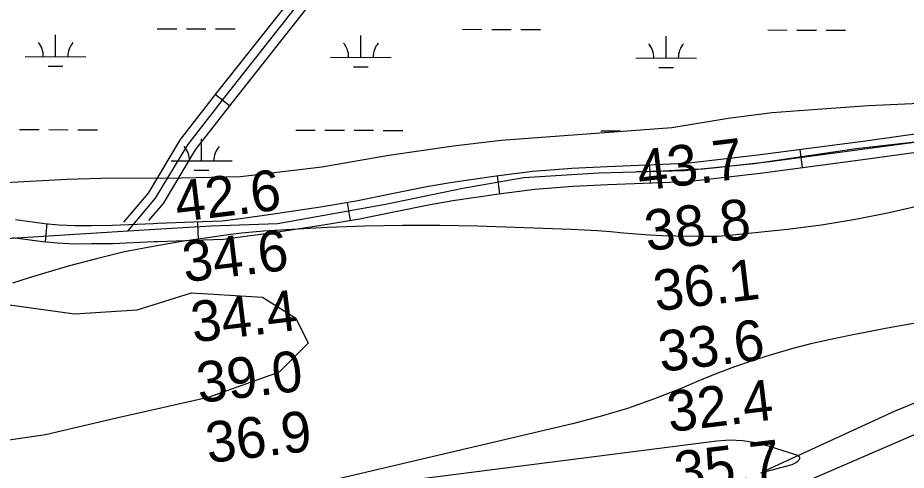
# Model space of a CAD drawing. Extents: x 3219052 to 3256913, y 800770 to 826146.
# Drawn here: x 3224915 to 3226376, y 816866 to 817611 of the extents above; entities that cross this region are included whole.
import ezdxf

# ---------------------------------------------------------------- set-up
doc = ezdxf.new("R2010")
doc.units = 0
for name, color, linetype in [('V-RIVR-IDEN', 7, 'Continuous'), ('V-RIVR-RANG', 7, 'Continuous'), ('V-ROAD-CNTR', 7, 'Continuous'), ('V-SITE-VEGE', 7, 'Continuous'), ('V-TOPO-MAJR', 7, 'Continuous'), ('V-TOPO-MINR', 7, 'Continuous'), ('V-WETL-SWMP', 7, 'Continuous')]:
    doc.layers.add(name, color=color, linetype=linetype)

msp = doc.modelspace()

# ---------------------------------------------------------------- linework, layer by layer
at = {"layer": 'V-ROAD-CNTR'}
for p, q in [((3225263.4, 817465.8), (3225239.7, 817484.1)), ((3226200.9, 817393.8), (3226204.8, 817364.1)), ((3225953.7, 817368.6), (3225954.9, 817338.7)), ((3225703.2, 817350.5), (3225707.1, 817320.7)), ((3225456.6, 817306.6), (3225461.6, 817277)), ((3224963, 817271.9), (3224960.2, 817242)), ((3225210.8, 817274.8), (3225211.9, 817244.8))]:
    msp.add_line(p, q, dxfattribs=at)
for points in [[(3225096.1, 817259.6), (3225141.6, 817313.4), (3225194.6, 817401.5), (3225255.4, 817479.9), (3225392.8, 817654.3), (3225582.5, 817917.4), (3225715.9, 818121.1), (3225842, 818314.9), (3225902.1, 818437.2), (3225914.8, 818521.2), (3225906.7, 818658.5), (3225884.4, 818797), (3225888.1, 818985.3), (3225907, 819138.9), (3225923.6, 819231.3), (3225968.7, 819301), (3226035.2, 819352.3), (3226084, 819382.3), (3226185.7, 819414.7), (3226404.9, 819451.8)], [(3226408.4, 819437.2), (3226189.2, 819400), (3226090.3, 819368.6), (3226043.7, 819339.9), (3225979.9, 819290.7), (3225937.8, 819225.7), (3225921.8, 819136.7), (3225903.1, 818984.3), (3225899.4, 818798.1), (3225921.7, 818660.2), (3225929.8, 818520.5), (3225916.5, 818432.7), (3225855.1, 818307.5), (3225728.5, 818112.9), (3225594.9, 817908.9), (3225404.8, 817645.3), (3225267.2, 817470.7), (3225207, 817393), (3225153.9, 817304.6), (3225130.3, 817276.8)], [(3225872.4, 818777.2), (3225891.8, 818656.9), (3225899.7, 818521.9), (3225887.6, 818441.7), (3225829, 818322.3), (3225703.3, 818129.3), (3225570.2, 817925.9), (3225380.9, 817663.3), (3225243.6, 817489.1), (3225182.2, 817410), (3225129.4, 817322.1), (3225088.8, 817274.2)], [(3224911.6, 817278.6), (3224959.1, 817272.2), (3224982.7, 817270), (3225009.1, 817268.5), (3225036.1, 817268.8), (3225070.4, 817269.3), (3225138, 817272.2), (3225144.9, 817272.5), (3225219.3, 817275.1), (3225250.9, 817276.2), (3225281.3, 817280.2), (3225331.6, 817287.1), (3225413.1, 817299.3), (3225471.5, 817309.1), (3225530.2, 817321.3), (3225587.4, 817332.6), (3225625.9, 817339.3), (3225701.7, 817350.3), (3225761.9, 817358.2), (3225825.8, 817363.2), (3225884.2, 817365.8), (3226014.1, 817371.1), (3226131.8, 817384.8), (3226308.8, 817408), (3226503.1, 817435.2)], [(3223234.1, 816639.7), (3223607.5, 816776.5), (3224116.6, 816952.2), (3224455.2, 817073.6), (3224587.9, 817135.7), (3224711, 817202), (3224812.2, 817235.9), (3224896.2, 817247), (3225122.8, 817261.3), (3225233.3, 817267.9), (3225342, 817271.9), (3225519.9, 817303.8), (3225646.7, 817330.2), (3225747.4, 817347.9), (3225869.8, 817355.1), (3226011.4, 817359), (3226126, 817370.9), (3226293.3, 817395.4), (3226462.7, 817414.3)], [(3224907.2, 817248.9), (3224955.7, 817242.4), (3224980.4, 817240.1), (3225008.4, 817238.5), (3225036.5, 817238.8), (3225071.3, 817239.3), (3225139.1, 817242.2), (3225146, 817242.5), (3225220.4, 817245.1), (3225253.3, 817246.3), (3225285.3, 817250.5), (3225335.8, 817257.4), (3225417.8, 817269.6), (3225477, 817279.6), (3225536.2, 817291.9), (3225592.9, 817303.1), (3225630.6, 817309.7), (3225705.8, 817320.6), (3225765, 817328.4), (3225827.6, 817333.2), (3225885.5, 817335.9), (3226016.5, 817341.1), (3226135.5, 817355), (3226312.8, 817378.3), (3226507.1, 817405.4)]]:
    msp.add_lwpolyline(points, dxfattribs=at)
at = {"layer": 'V-SITE-VEGE'}
for p, q in [((3225111.5, 817130.1), (3225200.7, 817157.6)), ((3225200.7, 817157.6), (3225317.4, 817150.7)), ((3225317.4, 817150.7), (3225372.3, 817116.4)), ((3224857.6, 817143.9), (3225008.5, 817123.3)), ((3225008.5, 817123.3), (3225111.5, 817130.1)), ((3225372.3, 817116.4), (3225392.8, 817075.2)), ((3225392.8, 817075.2), (3225344.8, 817027.1)), ((3226356.8, 816962.9), (3226530, 817035.8)), ((3225344.8, 817027.1), (3225228.1, 816985.9)), ((3225228.1, 816985.9), (3225077.2, 816951.6)), ((3226145.4, 816865.9), (3226356.8, 816962.9)), ((3225077.2, 816951.6), (3224960.5, 816924.1)), ((3224960.5, 816924.1), (3224864.4, 816910.4))]:
    msp.add_line(p, q, dxfattribs=at)
at = {"layer": 'V-TOPO-MAJR'}
for points in [[(3226403.4, 817110.4), (3226341.8, 817099), (3226283.2, 817087.9), (3226251.1, 817081.2), (3226219.1, 817073.9), (3226187.3, 817065.6), (3226155.8, 817056.6), (3226152.2, 817055.5), (3226122.7, 817046.1), (3226093.4, 817036), (3226064.5, 817025), (3226035.8, 817013.4), (3226005.9, 817000.7), (3225962, 816983.4), (3225917.7, 816967.7), (3225872.6, 816954.2), (3225827, 816942.2), (3225358.7, 816831.9)], [(3225412.1, 816830.8), (3226064.4, 816914.4), (3226085.8, 816915.7), (3226107, 816915.1), (3226127.9, 816911.6), (3226148.6, 816906.3), (3226196.9, 816890.5), (3226198.9, 816888.9), (3226200.1, 816887.1), (3226200.1, 816885), (3226199.3, 816882.6), (3226196.9, 816880.1), (3226194.2, 816877.9), (3226191.2, 816876.3), (3226188, 816875), (3226136.5, 816860.9)]]:
    msp.add_lwpolyline(points, dxfattribs=at)
at = {"layer": 'V-TOPO-MINR'}
for points in [[(3226856.4, 817467.8), (3226200.9, 817379.9), (3226176.2, 817376.7), (3226151.5, 817373.6), (3226126.8, 817370.6), (3226102.1, 817367.7), (3226063.4, 817363.4), (3226058, 817362.9), (3226052.6, 817362.4), (3226047.2, 817361.9), (3226041.7, 817361.6), (3226014.4, 817360.1), (3225995.3, 817359.1), (3225976.2, 817358.3), (3225957.1, 817357.7), (3225938, 817357.2), (3225931.6, 817357.1)], [(3226402.7, 817302.2), (3226347.6, 817289.4), (3226292.2, 817278.3), (3226236.4, 817269.4), (3226180.4, 817262.2), (3226090.4, 817252.5), (3226078.5, 817251.4), (3226066.5, 817250.7), (3226054.5, 817250.3), (3226042.5, 817250.3), (3225996.4, 817251), (3225975, 817251.6), (3225953.5, 817252.6), (3225932.2, 817254.2), (3225910.8, 817256.1), (3225889.4, 817258.2), (3225868, 817259.9), (3225846.6, 817261.1), (3225825.2, 817262.1), (3225671, 817267.4), (3225609.3, 817268.7), (3225547.7, 817268.9), (3225486, 817267.6), (3225424.4, 817265.1), (3225337.2, 817260.6), (3225319.2, 817259.4), (3225301.2, 817257.9), (3225283.2, 817255.9), (3225265.2, 817253.6), (3225184.7, 817242.1), (3225137.5, 817234.3), (3225090.7, 817225.2), (3225044.3, 817214), (3224998.2, 817201.6), (3224961.1, 817190.7), (3224933.8, 817182.5), (3224906.6, 817174)], [(3226896.8, 817144.4), (3226152, 816821.4), (3226120.6, 816812.8), (3226089.1, 816804.5), (3225441.5, 816495), (3225419.1, 816488.8), (3225396.7, 816482.8), (3224771.1, 816192.5), (3224740.2, 816182.9), (3224332.4, 816001.6), (3224294, 815985.5), (3224176.4, 815938.5), (3224136, 815922.5), (3224095.5, 815906.7), (3224060.2, 815893.2)]]:
    msp.add_lwpolyline(points, dxfattribs=at)
at = {"layer": 'V-WETL-SWMP'}
for p, q in [((3225144.4, 817592.5), (3225176.4, 817592.5)), ((3225192.4, 817592.4), (3225224.4, 817592.4)), ((3225240.4, 817592.3), (3225272.4, 817592.3)), ((3225646.3, 817591.5), (3225678.3, 817591.4)), ((3225694.3, 817591.4), (3225726.3, 817591.3)), ((3225742.3, 817591.3), (3225774.3, 817591.2)), ((3226148.2, 817590.4), (3226180.2, 817590.3)), ((3226196.2, 817590.3), (3226228.2, 817590.2)), ((3226244.2, 817590.2), (3226276.2, 817590.1)), ((3224977.2, 817546.4), (3224977.3, 817582.4)), ((3225479.1, 817545.4), (3225479.2, 817581.4)), ((3225981.1, 817544.3), (3225981.1, 817580.3)), ((3224927.2, 817546.5), (3225027.2, 817546.3)), ((3225429.1, 817545.5), (3225529.1, 817545.3)), ((3225931.1, 817544.4), (3226031.1, 817544.2)), ((3224965.2, 817531), (3224989.2, 817531)), ((3225467.1, 817530), (3225491.1, 817529.9)), ((3225969, 817528.9), (3225993, 817528.9)), ((3226313.9, 817465.9), (3226434.7, 817471.9)), ((3226155.6, 817454.6), (3226229.3, 817460.2)), ((3226229.3, 817460.2), (3226313.9, 817465.9)), ((3225990.2, 817430), (3226083.1, 817445.4)), ((3226083.1, 817445.4), (3226155.6, 817454.6)), ((3225709.9, 817409), (3225990.2, 817430)), ((3224918.1, 817426.5), (3224950.1, 817426.4)), ((3224966.1, 817426.4), (3224998.1, 817426.3)), ((3225014.1, 817426.3), (3225046.1, 817426.2)), ((3225372.1, 817425.5), (3225404.1, 817425.5)), ((3225420.1, 817425.4), (3225452.1, 817425.4)), ((3225468.1, 817425.3), (3225500.1, 817425.3)), ((3225516.1, 817425.2), (3225548.1, 817425.2)), ((3225874, 817424.5), (3225906, 817424.4)), ((3225217.4, 817375.1), (3225217.4, 817411.1)), ((3225525.1, 817384.2), (3225631.3, 817399.8)), ((3225631.3, 817399.8), (3225709.9, 817409)), ((3225719.3, 817409.7), (3225719.3, 817410.1)), ((3225415.2, 817365), (3225525.1, 817384.2)), ((3225167.4, 817375.2), (3225267.4, 817375)), ((3225205.3, 817359.7), (3225229.3, 817359.7)), ((3225281.2, 817349.1), (3225415.2, 817365)), ((3224884.7, 817339.1), (3224995.9, 817345)), ((3224995.9, 817345), (3225070.8, 817347)), ((3225070.8, 817347), (3225160.3, 817346.7)), ((3225160.3, 817346.7), (3225281.2, 817349.1))]:
    msp.add_line(p, q, dxfattribs=at)
for centre, start, end in [((3224922, 817547), 359.1081, 40.6518), ((3225032.5, 817546.8), 139.1081, 180.6517), ((3225423.9, 817546), 359.1081, 40.6518), ((3225534.4, 817545.7), 139.1081, 180.6517), ((3225925.8, 817544.9), 359.1081, 40.6518), ((3226036.3, 817544.7), 139.1081, 180.6517), ((3225162.1, 817375.7), 359.1081, 40.6518), ((3225272.6, 817375.5), 139.1081, 180.6517)]:
    msp.add_arc(centre, 35.2, start, end, dxfattribs=at)

# ---------------------------------------------------------------- texts
at = {"layer": 'V-RIVR-IDEN'}
msp.add_text(' September', height=83, rotation=24.6124, dxfattribs=at).set_placement((3226223.8, 816603.9))
at = {"layer": 'V-RIVR-RANG'}
for s, rotation, p in [('43.7', 6.9283, (3225937.5, 817325.5)), ('42.6', 6.8883, (3225177.6, 817274.3)), ('38.8', 6.9283, (3225949.8, 817226.2)), ('34.6', 6.8883, (3225189.8, 817175.1)), ('36.1', 6.9283, (3225964.4, 817127.3)), ('34.4', 6.8883, (3225203.9, 817076)), ('33.6', 6.9283, (3225972.5, 817027.5)), ('39.0', 6.8883, (3225213.3, 816976.4)), ('32.4', 6.9283, (3225986.7, 816928.5)), ('36.9', 6.8883, (3225228.2, 816877.5)), ('35.7', 6.9283, (3225999, 816829.3))]:
    msp.add_text(s, height=67, rotation=rotation, dxfattribs=at).set_placement(p)

doc.saveas('drawing.dxf')
